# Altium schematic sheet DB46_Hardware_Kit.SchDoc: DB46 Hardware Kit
size A4; Organization: Altium Limited.; Address1: Level 3, 12a Rodborough Rd; Address2: Frenchs Forest 2086; Address3: NSW; Address4: AUSTRALIA; DocumentNumber: 9; SheetNumber: 9; SheetTotal: 23
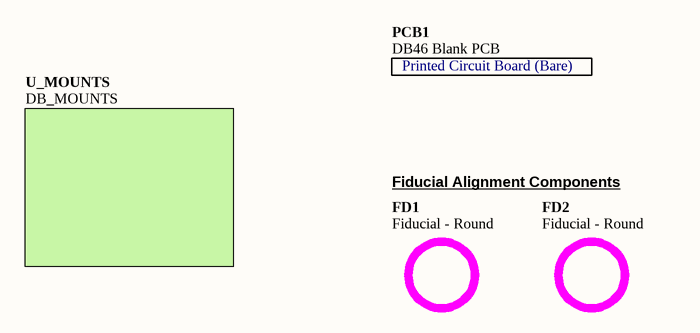
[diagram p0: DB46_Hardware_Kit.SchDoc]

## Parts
FD1  Fiducial - Round  [FIDUCIAL ROUND]
FD2  Fiducial - Round  [FIDUCIAL ROUND]
PCB1  DB46 Blank PCB  [DB46 Blank PCB]

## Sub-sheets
U_MOUNTS = DB_MOUNTS: no entries

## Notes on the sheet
- Fiducial Alignment Components

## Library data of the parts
FD1 FD2 = D-000-0005: Fiducial - Round 1.5mm Top-Bottom
PCB1 = D-810-0034: DB46 Blank PCB - Daughter Board; ProjectPath: DB46.PrjPCB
